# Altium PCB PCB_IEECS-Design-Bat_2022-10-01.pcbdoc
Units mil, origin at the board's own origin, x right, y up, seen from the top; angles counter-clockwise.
Board outline 3665.03 x 2799.77 mil, 2 copper layers (Top Layer, Bottom Layer); 64 components, 39 nets, 166 pads, 43 vias.
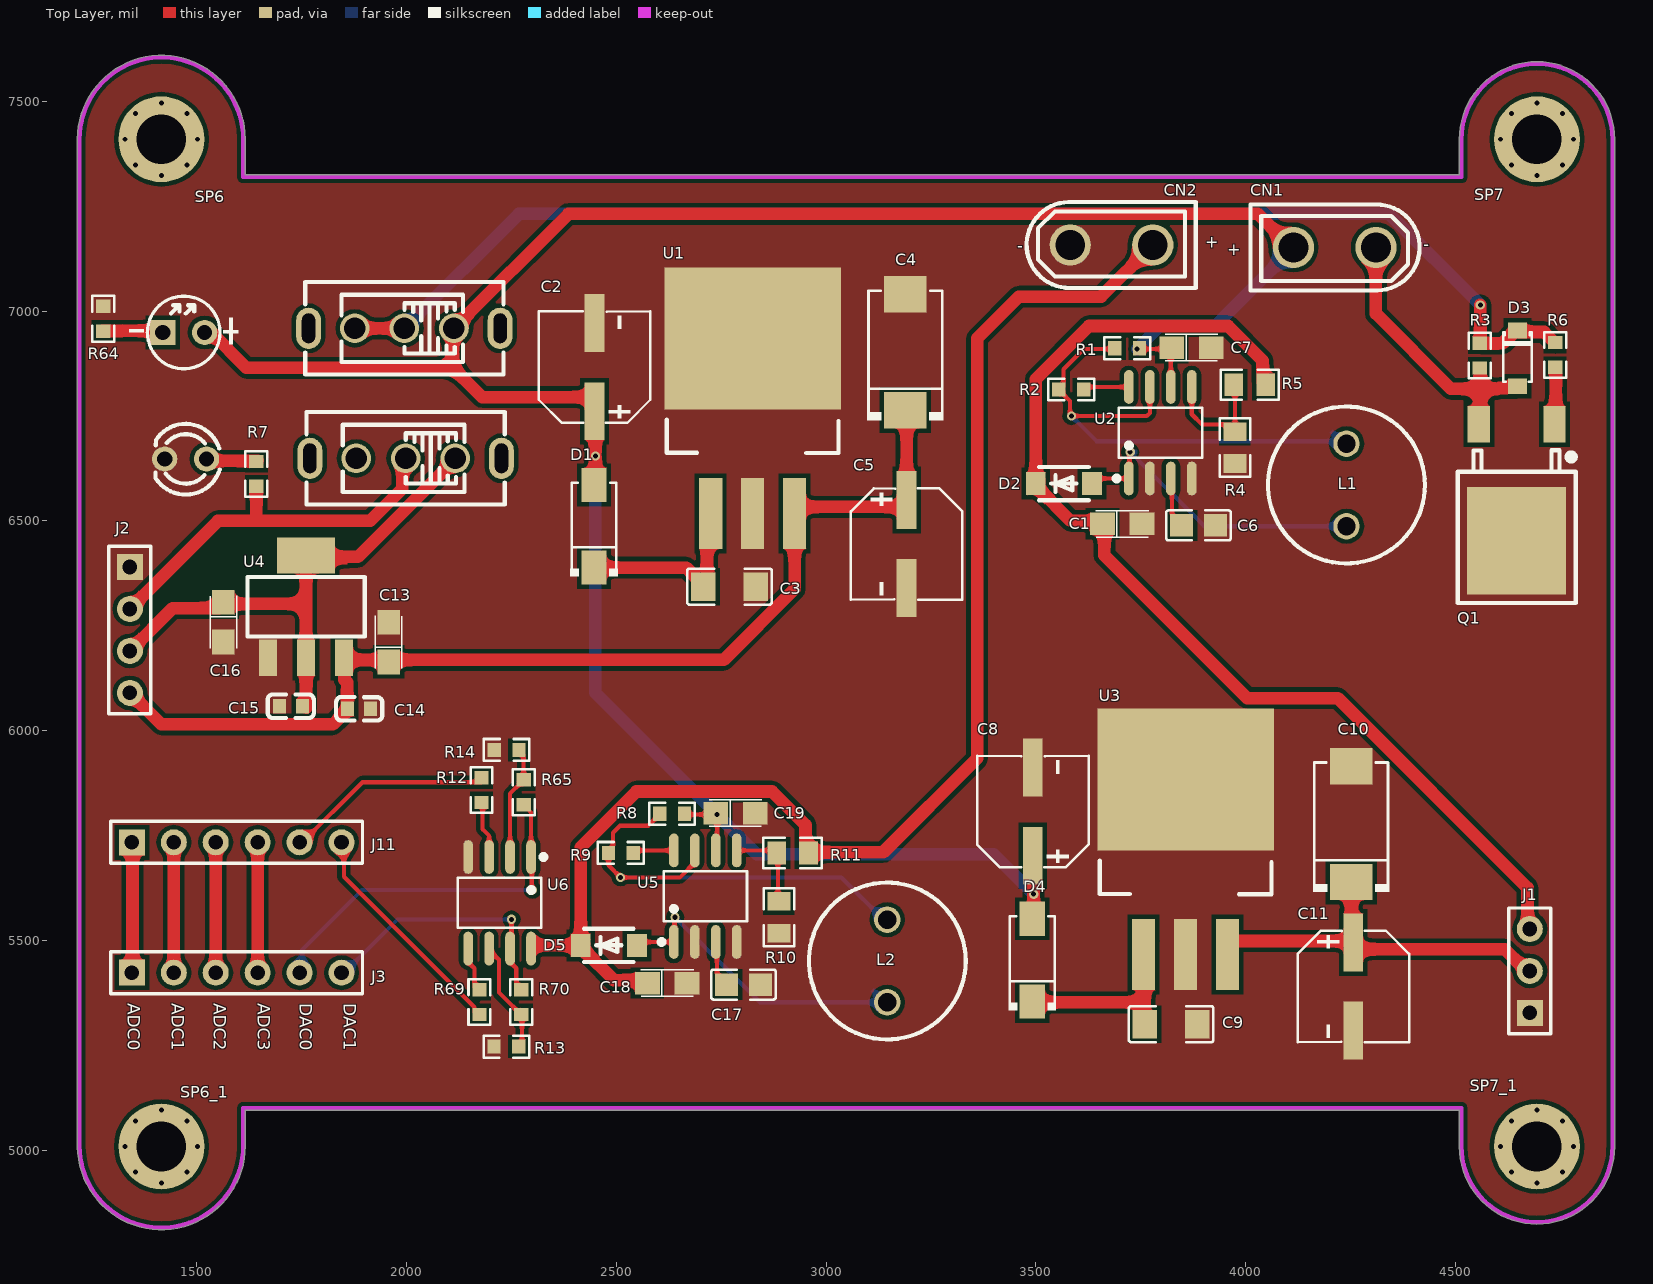
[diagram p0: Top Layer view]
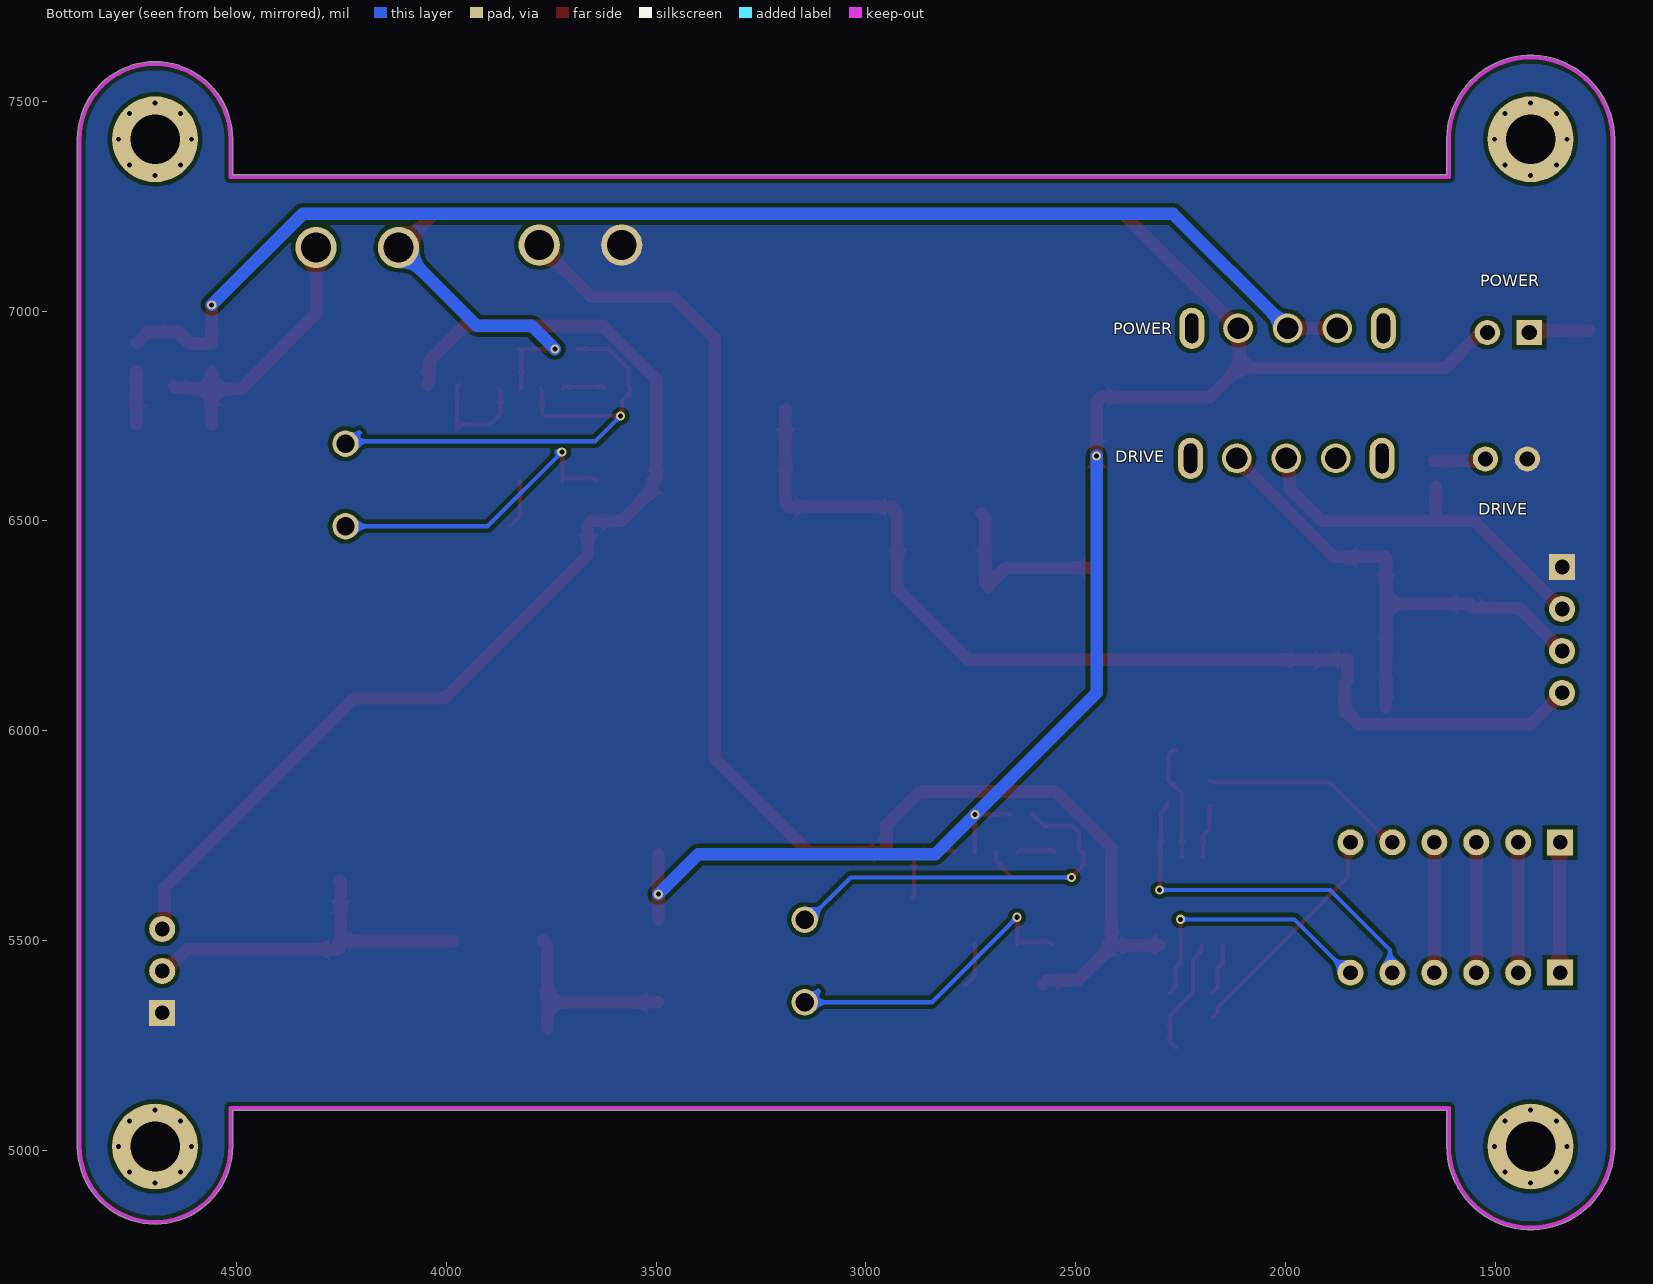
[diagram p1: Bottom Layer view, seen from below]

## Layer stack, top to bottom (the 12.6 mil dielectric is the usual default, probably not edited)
Top Solder: solder mask 0.4, Solder Resist, Dk 3.5
Top Layer: signal copper 1.4
Dielectric1: dielectric 12.6, FR-4, Dk 4.8
Bottom Layer: signal copper 1.4
Bottom Solder: solder mask 0.4, Solder Resist, Dk 3.5

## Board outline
1214.98,5009.8 cw(c1415,5010) 1214.98,5010 cw(c1220,5010) 1214.98,5010.03 1214.98,7410 cw(c1415,7410) 1615.02,7410 1615.02,7325.01 4509.99,7325.01 4509.99,7410 cw(c4695,7410) 4880.01,7410 4880.01,5008.43 cw(c4695,5008.43) 4509.99,5008.43 4509.99,5094.98 1615.02,5094.98 1615.02,5010 cw(c1415,5010) 1214.99,5008.13 cw(c1220,5008.43) 1214.98,5008.43

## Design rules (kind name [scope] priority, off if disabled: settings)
Clearance [All] p1: gap=10 ignorepadtopadclearanceinfootprint=FALSE except(0: Arc-Hole Track-Hole SMDPad-Hole THPad-Hole Via-Hole Fill-Hole Poly-Hole Region-Hole Text-Hole)
Height [All] p1: minheight=-35795.94 maxheight=71537.31 prefheight=71537.31
PolygonConnect [All] p1: connectstyle=Direct reliefconductorwidth=10 reliefentries=4 polygonreliefangle="90 Angle" airgapwidth=10
RoutingVias [All] p1: holewidth=28 width=50 viastyle="Through Hole" minholewidth=28 minwidth=50 maxholewidth=28 maxwidth=50
SolderMaskExpansion [All] p1: expansion=4
Width [All] p1: maxlimit=30 minlimit=10 preferedwidth=10 minimp=50.000000 maximp=50.000000 favimp=50.000000
29 further rules are at their usual default settings.

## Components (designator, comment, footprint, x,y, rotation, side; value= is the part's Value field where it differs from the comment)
C1 "10u" CASE-A-3216 3710,6490 r0 top
C2 "100uF" 110uf 2450,6870 r0 top
C3 "470nF" CAP1206 2770,6350 r0 top
C4 "22uF" CAP-SMD 3190,6895 r0 top
C5 "220uF" 220uf 3185,6440 r0 top
C6 "470pF" CAP0805 3890.55,6490 r0 top
C7 "10u" CASE-A-3216 3875,6910 r0 top
C8 "100uF" 110uf 3495,5809.84 r0 top
C9 "470nF" CAP1206 3823.09,5306.6 r0 top
C10 "22uF" CAP-SMD 4253.37,5770 r0 top
C11 "220uF" 220uf 4250,5385 r0 top
C13 "10u" CASE-A-3216 1960,6215 r90 top
C14 "100nf" CAP0603 1885.43,6055 r180 top
C15 "100nf" CAP0603 1725,6055 r0 top
C16 "10u" CASE-A-3216 1560,6255 r270 top
C17 "470pF" CAP0805 2805.55,5395 r0 top
C18 "10u" CASE-A-3216 2625,5395 r0 top
C19 "10u" CASE-A-3216 2787.76,5800 r0 top
CN1 "XT30UPB-M" XT30 4200,7140 r90 top
CN2 "XT30UPB-M" XT30 3693.27,7170 r270 top
D1 "SS54_C727065" SS54 2450,6485 r270 top
D2 "1N5819HW-7-F" Diode 3575,6595.85 r0 top
D3 "BZT52C16_C216724" BTZ52C16 4650,6886.43 r270 top
D4 "SS54_C727065" SS54 3495,5450.69 r270 top
D5 "1N5819HW-7-F" Diode 2490,5495 r0 top
DRIVE "TJ-L3FYTXHAMCGLFLC0A-A5" LED-LARGE-2 1470.35,6645 r0 bottom (schematic designator LED3)
DRIVE "SS-12F44-G5" Switch 2000.35,6645 r0 bottom (schematic designator SW2)
J1 "HDR-M-2.54_1x3" Pin1X3 4680,5425 r0 top
J2 "HDR-M-2.54_1x4" Pin1X4 1335.86,6240.59 r90 top
J3 "HDR-M-2.54_1x6" Pin1x6 1598.45,5415 r0 top
J11 "HDR-M-2.54_1x6" Pin1x6 1598.45,5725.85 r0 top
L1 "470uH" L 4240,6580 r0 top
L2 "470uH" L 3145,5445 r0 top
POWER "TJ-L3FYTGHGMCGLFLC2G-A5" LED-LARGE-1 1475.35,6950 r180 bottom (schematic designator LED1)
POWER "SS-12F44-G5" Switch 1997.23,6955 r0 bottom (schematic designator SW1)
Q1 "IRLR7843TRPBF" IRLR7843 4650,6560.53 r0 top
R1 "0.22R" RES0603 3710,6910 r0 top
R2 "180R" RES0603 3592.64,6815 r180 top
R3 "100k" RES0603 4560,6886.43 r90 top
R4 "2k" RES0805 3975,6680 r270 top
R5 "14k" RES0805 4005,6825 r0 top
R6 "1k" RES0603 4740,6887.92 r90 top
R7 "330" RES0603 1640,6620 r270 top
R8 "0.22R" RES0603 2625,5800 r0 top
R9 "180R" RES0603 2518.51,5710 r180 top
R10 "1.5k" RES0805 2887.76,5560 r270 top
R11 "13k" RES0805 2915,5708.41 r0 top
R12 "10k" RES0603 2180,5850.35 r90 top
R13 "15k" RES0603 2230,5245 r0 top
R14 "15k" RES0603 2230.34,5952.42 r0 top
R64 "510" RES0603 1275,6990 r270 top
R65 "30k" RES0603 2281.05,5845 r90 top
R69 "10k" RES0603 2175,5345 r90 top
R70 "30k" RES0603 2275,5345 r90 top
SP6 "M3铜柱" M3-MountHole-Plated 1415,7410 r0 top (schematic designator SP2)
SP6_1 "M3铜柱" M3-MountHole-Plated 1415,5008.43 r0 top (schematic designator SP2)
SP7 "M3铜柱" M3-MountHole-Plated 4695,7410 r0 top (schematic designator SP2)
SP7_1 "M3铜柱" M3-MountHole-Plated 4695,5008.43 r0 top (schematic designator SP2)
U1 "LM2940S-5.0/NOPB" LM2940S 2782.7,6756.79 r0 top
U2 "MC34063ADR" MC34063 3800,6705 r0 top
U3 "LM2940S-5.0/NOPB" LM2940S 3815,5705 r0 top
U4 "AMS1117-3.3_C347222" AMS1117 1760,6290 r0 top
U5 "MC34063ADR" MC34063 2715,5600 r0 top
U6 "LM358DR2G" LM358 2225,5593.5 r180 top

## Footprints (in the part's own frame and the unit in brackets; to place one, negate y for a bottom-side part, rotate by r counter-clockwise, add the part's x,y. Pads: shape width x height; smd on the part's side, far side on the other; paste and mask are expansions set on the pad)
110uf [mm]
  rect 1.2x3.5 smd: 1(-0.053,-2.75) 2(-0.053,2.59)
  silkscreen extent -3.43,-3.46 3.32,3.3, body extent -3.37,-3.73 3.23,4.07, height 7.75
220uf [mm]
  rect 1.2x3.5 smd: 1(0.178,2.793) 2(0.178,-2.547)
  silkscreen extent -3.2,-3.25 3.55,3.5, body extent -3.1,-3.82 3.5,3.98, height 7.75
AMS1117 [mm]
  rect 1.1x2.2 smd: 1(-2.297,-2.959) 2(0.003,-2.959) 3(2.303,-2.959)
  rect 3.5x2.2 smd: 4(0.003,3.238)
  silkscreen extent -3.55,-1.66 3.55,1.94, body extent -3.22,-3.43 3.28,3.68, height 1.75
BTZ52C16 [mm]
  rect 0.95x1.15 smd: 1(-1.723,-0.043) 2(1.662,-0.043)
  silkscreen extent -1.61,-0.91 1.38,0.82, body extent -1.93,-0.84 1.75,0.76, height 1.22
CAP0603 [mm]
  rect 0.8x0.9 smd: 1(-0.725,0.076) 2(0.675,0.076)
  silkscreen extent -1.43,-0.63 1.36,0.79, body extent -0.93,-0.32 0.67,0.48, height 0.8
CAP0805 [mm]
  rect 1.41x1.35 smd: 1(0.965,-0.015) 2(-1.095,-0.015)
  silkscreen extent -2.03,-0.92 1.9,0.89, body extent -1.14,-0.69 0.86,0.61, height 1.3
CAP1206 [mm]
  rect 1.485x1.728 smd: 1(1.583,-0.168) 2(-1.602,-0.168)
  silkscreen extent -2.57,-1.26 2.55,0.92, body extent -1.68,-0.96 1.52,0.64, height 1.3
CAP-SMD [mil]
  rect 102.05x86.91 smd: 1(-1.2,-130.94) 2(-1.2,145.54)
  silkscreen extent -92,-154 89,154, body extent -86,-140 84,147, height 167
CASE-A-3216 [mil]
  rect 59.05x53.5 smd: 1(-51.07,3.1) 2(43.42,3.1)
  silkscreen extent -67,-28 59,35, body extent -67,-30 59,33, height 67
Diode [mm]
  rect 1.2x1.4 smd: 1(1.499,-0.177) 2(-1.901,-0.177)
  silkscreen extent -1.7,-1.18 1.3,0.82, body extent -1.95,-1.15 1.7,0.65, height 0.81
IRLR7843 [mm]
  rect 1.35x2.2 smd: 1(2.206,4.319) 3(-2.374,4.319)
  rect 6x6.5 smd: 4(-0.084,-2.748)
  silkscreen extent -3.66,-6.51 3.49,2.74, body extent -3.3,-5.41 3.2,4.51
L [mm]
  round 1.6 hole 1.1: 1(0.02,-2.355) 2(0.02,2.645)
  silkscreen extent -4.73,-4.6 4.77,4.89, body extent -4.7,-4.61 4.81,4.89, height 12.5
LED-LARGE-1 [mil]
  rect 60x60 hole 36: 1(56.95,-0.6)
  round 60 hole 36: 2(-43.05,-0.6)
  body extent -55,-79 87,75, height 118
LED-LARGE-2 [mil]
  round 60 hole 36: 1(52.71,-2.7) 2(-47.29,-2.7)
  body extent -77,-81 65,73, height 118
LM358 [mm]
  oval 0.588x2.045 smd: 1(-1.819,-2.671) 2(-0.549,-2.671) 3(0.721,-2.671) 4(1.991,-2.671) 5(1.991,2.874) 6(0.721,2.874) 7(-0.549,2.874) 8(-1.819,2.874)
  silkscreen extent -2.72,-2.82 2.61,1.62, body extent -2.33,-2.9 2.48,3.1, height 1.72
LM2940S [mm]
  rect 1.4x4.3 smd: 1(-1.466,-6.073) 2(1.074,-6.073) 3(3.614,-6.073)
  rect 10.7x8.6 smd: 4(1.074,4.527)
  silkscreen extent -4.13,-2.41 6.27,-0.39, body extent -4.05,-6.57 6.15,7.66, height 4.5
M3-MountHole-Plated [mm]
  round 5.2 hole 3: 1(0,0)
MC34063 [mm]
  oval 0.588x2.045 smd: 1(-1.981,-2.639) 2(-0.711,-2.639) 3(0.559,-2.639) 4(1.829,-2.639) 5(1.829,2.906) 6(0.559,2.906) 7(-0.711,2.906) 8(-1.981,2.906)
  silkscreen extent -2.88,-2.79 2.45,1.66, body extent -2.46,-2.81 2.35,3.19, height 1.72
Pin1X3 [mil]
  rect 62x62 hole 35: 1(-2.14,-98)
  round 62 hole 35: 2(-2.14,2) 3(-2.14,102)
  silkscreen extent -52,-148 48,152, body extent -52,-148 48,152, height 335
Pin1X4 [mil]
  rect 62x62 hole 35: 1(149.41,-4.14)
  round 62 hole 35: 2(49.41,-4.14) 3(-50.59,-4.14) 4(-150.59,-4.14)
  silkscreen extent -201,-54 199,46, body extent -205,-54 195,46, height 335
Pin1x6 [mil]
  rect 62x62 hole 35: 1(-253.74,7.86)
  round 62 hole 35: 2(-153.74,7.86) 3(-53.74,7.86) 4(46.26,7.86) 5(146.26,7.86) 6(246.26,7.86)
  silkscreen extent -304,-42 296,58, body extent -305,-45 295,125, height 335
RES0603 [mil]
  rect 31.75x34.02 smd: 1(-21.8,1.59) 2(37.51,1.59)
  silkscreen extent -47,-24 62,28, body extent -21,-16 42,16, height 31
RES0805 [mil]
  rect 44.59x54.21 smd: 1(43.14,-0.2) 2(-32.94,-0.2)
  silkscreen extent -64,-36 74,36, body extent -37,-25 42,26, height 24
SS54 [mil]
  rect 81.2x60.59 smd: 1(-100.77,-3.33) 2(96.37,-3.33)
  silkscreen extent -106,-60 117,53, body extent -100,-58 104,53, height 83
Switch [mm]
  round 1.8 hole 1.3: 1(2.93,-0.107) 2(-0.07,-0.107) 3(-3.07,-0.107)
  oval 1.5x2.5 hole 0.8 slot 1.8 at 90 deg: 4(-5.87,-0.107) 5(5.73,-0.107)
  body extent -6.12,-3.27 5.98,3.06, height 11.31
XT30 [mm]
  round 2.5 hole 1.8: 1(0.305,-2.822) 2(0.305,2.178)
  silkscreen extent -2.3,-5.46 2.91,4.78, body extent -2.3,-5.35 5.84,4.85, height 10.7

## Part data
SP6 SP6_1 SP7 SP7_1: library part 铜柱小焊盘, "铜柱"

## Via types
v1: diameter 23.62, hole 11.81, Top Layer to Bottom Layer, 32 vias
v2: diameter 22, hole 12, Top Layer to Bottom Layer, tented both sides, 11 vias

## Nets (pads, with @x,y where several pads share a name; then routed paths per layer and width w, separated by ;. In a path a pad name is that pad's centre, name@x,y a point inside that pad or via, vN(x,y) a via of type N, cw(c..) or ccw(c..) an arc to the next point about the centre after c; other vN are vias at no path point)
ADC-0: J3.1 J11.1 | length 312.6
  Top Layer w30: J3.1@1348.45,5415 1346.3,5417.15 1346.3,5723.7 J11.1@1348.45,5725.85
ADC-1: J3.2 J11.2 | length 313.9
  Top Layer w30: J3.2@1448.45,5415 1444.71,5418.74 1444.71,5722.1 J11.2@1448.45,5725.85
ADC-2: J3.3 J11.3 | length 313.9
  Top Layer w30: J3.3@1548.45,5415 1544.71,5418.74 1544.71,5722.1 J11.3@1548.45,5725.85
ADC-3: J3.4 J11.4 | length 313.9
  Top Layer w30: J3.4@1648.45,5415 1644.71,5418.74 1644.71,5722.1 J11.4@1648.45,5725.85
C6_2: C6.2 U2.3 | length 119.1
  Top Layer w10: U2.3@3825,6595.85 3824.51,6595.36 3824.51,6566.36 3824.7,6566.18 3824.7,6510.98 3845.67,6490 C6.2@3850,6490
D4_2: C9.2 D4.2 U3.1 | length 476.5
  Top Layer w30: D4.2@3495,5352.12 3759.61,5352.12 ; C9.2@3759.61,5290.69 3759.61,5352.12 ; U3.1@3769.86,5498.37 3759.61,5488.12 3759.61,5352.12
DAC-0-O: J11.5 R12.2 | length 498.3
  Top Layer w10: J11.5@1748.45,5725.85 1748.45,5730.83 1894.6,5876.98 2176.98,5876.98 R12.2@2180,5880
DAC-0-OUT: J3.5 R65.1 U6.1 | length 928
  Top Layer w10: R65.1@2278.41,5828.2 2284.1,5822.51 R65.1@2284.1,5817.33 ; R65.1@2280,5820.35 2281.08,5820.35 R65.1@2284.1,5817.33 ; U6.1 U6.1@2296.6,5730.89 ; v2(2300,5620) 2298.3,5621.7 2298.3,5698.3 2300,5700 2300,5727.49 U6.1@2296.6,5730.89 ; R65.1@2284.1,5817.33 2296.6,5804.83 U6.1@2296.6,5730.89
  Bottom Layer w10: J3.5@1748.45,5415 1750.27,5416.82 1750.27,5477.18 1893.09,5620 v2(2300,5620)
DAC-1-O: J11.6 R69.1 | length 545.8
  Top Layer w10: J11.6@1848.45,5725.85 1850.27,5724.03 1850.27,5651.56 2161.4,5340.42 2161.4,5328.95 R69.1@2175,5315.35
DAC-1-OUT: J3.6 R70.2 U6.7 | length 646.9
  Top Layer w10: v2(2250,5550) 2249.86,5549.86 2249.86,5487.14 2250,5487 2249.12,5486.12 2249.12,5445.59 2261.4,5433.31 2261.4,5388.26 R70.2@2275,5374.66
  Bottom Layer w10: J3.6@1848.45,5415 1848.45,5419.99 1978.46,5550 v2(2250,5550)
GND: C1.2 C2.2 C3.1 C4.2 C5.2 C6.1 C7.2 C8.2 C9.1 C10.2 C11.2 C13.2 C14.1 C15.1 C16.2 C17.1 C18.2 C19.2 CN2.1 DRIVE.2@1423.05,6647.7 J1.1 J2.1 Q1.4 R4.1 R10.1 R13.1 R14.1 R64.1 U1.2 U1.4 U2.2 U2.4 U3.2 U3.4 U4.1 U5.2 U5.4 U6.4
GNDIN: CN1.1 D3.2 Q1.3 R3.1 | length 696.8
  Top Layer w30: CN1.1@4308.43,7150 4310.88,7147.55 4310.88,6994.12 4490,6815 4560,6815 ; Q1.3@4559.84,6730.4 4560,6730.56 4560,6815 ; R3.1@4560,6854.93 4560,6815 ; D3.2@4650,6819.79 4647.49,6817.28 4604.71,6817.28 4602.43,6815 4560,6815
L1_1: D2.1 L1.1 U2.1 | length 747.6
  Top Layer w10: D2.1@3641.93,6595.85 3647.2,6601.12 3719.73,6601.12 3725,6595.85 3723.5,6597.35 3723.5,6662.65 v2(3725,6664.15)
  Bottom Layer w10: v2(3725,6664.15) 3901.88,6487.27 4234.3,6487.27 L1.1@4240,6481.57
L1_2: L1.2 R1.1 R2.2 U2.7 | length 1199.1
  Top Layer w10: R1.1 3686.61,6910 3614.47,6910 3566,6861.53 3566,6819.86 3561.14,6815 3561.14,6806.26 3581.31,6786.09 3581.31,6753.69 v2(3585,6750) 3764.59,6750 3772,6757.41 3772,6811.15 U2.7@3775,6814.15
  Bottom Layer w10: v2(3585,6750) 3644.85,6690.15 4228.27,6690.15 L1.2@4240,6678.42
LED1_2: POWER.1@1418.39,6949.4 R64.2 | length 151.5
  Top Layer w30: R64.2@1275.35,6953.51 1421.84,6953.51 POWER.1@1425.35,6950
NSLEEP: DRIVE.2@1997.57,6649.2 J2.2 R7.2 | length 926.4
  Top Layer w30: J2.2 1550,6500 1648.45,6500 ; R7.2 1641.59,6506.86 1648.45,6500 ; DRIVE.2@2000.35,6645 1989.75,6634.41 1989.75,6576.91 1912.84,6500 1648.45,6500
Q1_1: Q1.1 R6.1 | length 126.1
  Top Layer w30: R6.1@4740,6856.43 4740,6730.56 Q1.1@4740.16,6730.39
R2_1: R2.1 U2.8 | length 105.6
  Top Layer w10: R2.1@3624.13,6815 3624.13,6818.25 3625.31,6819.43 3719.73,6819.43 U2.8@3724.15,6815
R5_2: R4.2 R5.2 U2.5 | length 288.2
  Top Layer w10: U2.5@3875,6814.15 3872,6811.15 3872,6754.25 3896.01,6730.24 3962.81,6730.24 3975,6718.04 3975,6820 R5.2@3970,6825
R7_1: DRIVE.1@1523.05,6647.7 R7.1 | length 125.8
  Top Layer w30: DRIVE.1@1520.35,6645 1522.36,6642.99 R7.1@1645.35,6642.99
R12_1: R12.1 U6.3 | length 134.4
  Top Layer w10: R12.1@2180,5820.69 2181.09,5820.69 2181.09,5765 2196.6,5749.49 U6.3@2196.6,5703.4 ; U6.3 U6.3@2196.6,5703.4 ; U6.3@2200,5700 U6.3@2196.6,5703.4
R65_2: R14.2 R65.2 U6.2 | length 282.7
  Top Layer w10: U6.2 U6.2@2246.6,5703.4 ; U6.2@2247.99,5702.01 U6.2@2246.6,5703.4 ; R14.2@2260,5952.42 2268.32,5952.42 2278.73,5942 R65.2@2278.73,5881.79 ; R65.2 R65.2@2278.73,5881.79 ; U6.2@2246.6,5703.4 2246.6,5849.66 R65.2@2278.73,5881.79
R69_2: R69.2 U6.5 | length 123.4
  Top Layer w10: U6.5@2150,5487 2149.12,5486.12 2149.12,5445.59 2161.4,5433.31 2161.4,5388.26 R69.2@2175,5374.66
R70_1: R13.2 R70.1 U6.6 | length 280.4
  Top Layer w10: U6.6@2200,5487 2200,5474.58 2220.03,5454.56 2220.03,5375.45 2275,5320.48 2275,5258.6 2261.4,5245 R13.2@2259.66,5245
S$28: 
S$1126: 
SW1_3: D3.1 POWER.2@1994.46,6959.2 POWER.3 R3.2 R6.2 | length 3189.1
  Top Layer w30: POWER.3@1879.13,6955 1883.33,6959.2 1993.04,6959.2 POWER.2@1997.24,6955 ; v2(4560,7015) 4560,6923.56 4560.42,6923.14 4613.25,6923.14 4643.17,6953.06 4648.3,6953.06 4650.81,6950.55 4712.16,6950.55 4738.15,6924.56 R6.2@4740,6924.56
  Bottom Layer w30: POWER.2@1997.24,6955 1997.24,6961.97 2267.48,7232.21 4342.79,7232.21 v2(4560,7015)
U1_1: C3.2 D1.2 U1.1 | length 458.9
  Top Layer w30: D1.2@2450,6386.43 2452.2,6388.63 2666.47,6388.63 2706.91,6348.18 C3.2 ; C3.2@2708.51,6345 2715.96,6352.45 2715.96,6508.64 U1.1
U5_1: D5.1 L2.1 U5.1 | length 744.5
  Top Layer w10: D5.1@2556.93,5490 2563.05,5496.12 2633.04,5496.12 2639.15,5490 2638.5,5490.66 2638.5,5553.5 v2(2640,5555)
  Bottom Layer w10: v2(2640,5555) 2842.73,5352.27 3139.3,5352.27 L2.1@3145,5346.57
U5_3: C17.2 U5.3 | length 109.1
  Top Layer w10: U5.3@2740,5490.85 2739.51,5490.36 2739.51,5461.36 2739.7,5461.18 2739.7,5415.98 2760.67,5395 C17.2@2765,5395
U5_5: R10.2 R11.2 U5.5 | length 211.4
  Top Layer w10: U5.5@2790,5709.15 2790,5711.35 2793.07,5714.43 2878.88,5714.43 2885,5708.31 2885,5605 R10.2@2890,5600
U5_7: L2.2 R8.1 R9.2 U5.7 | length 1145.2
  Top Layer w10: R9.2 2480.99,5679.01 v2(2510,5650) 2651.25,5650 2690,5688.75 U5.7@2690,5709.15 ; R9.2@2487.01,5710 2491.87,5714.86 2491.87,5756.53 2508.4,5773.06 2575.8,5773.06 2603.2,5800.46 R8.1
  Bottom Layer w10: v2(2510,5650) 3036.09,5650 3142.67,5543.42 L2.2@3145,5543.42
U5_8: R9.1 U5.8 | length 94.7
  Top Layer w10: R9.1@2550,5710 2550,5713.25 2551.18,5714.43 2634.73,5714.43 U5.8@2639.15,5710
VCC: C2.1 C7.1 C8.1 C19.1 CN1.2 D1.1 D4.1 POWER.1@2112.57,6959.2 POWER.2@1518.39,6949.4 R1.2 R8.2 U2.6 U5.6 | length 6233.1
  Top Layer w10: R8.2@2656.5,5800 v2(2740,5800) 2740.33,5799.67 2740.33,5709.48 U5.6@2740,5709.15 ; v2(3741.5,6910) 3827.76,6910 3822,6904.24 U2.6 3822,6817.16 U2.6@3825,6814.15
  Top Layer w30: POWER.2@1525.35,6950 1532.9,6950 1617.9,6865 2110,6865 ; D1.1@2450,6583.57 v2(2450,6655) 2450,6784.42 2439.28,6795.14 2179.86,6795.14 2110,6865 ; D4.1@3495,5549.26 v2(3495,5610) C8.1@3495,5704.73 ; CN1.2@4111.58,7150 4029.37,7232.21 2385.59,7232.21 2115.35,6961.97 2115.35,6955 2110,6949.65 2110,6865
  Bottom Layer w30: v2(2450,6655) 2450,6090 v2(2740,5800) 2835,5705 3400,5705 v2(3495,5610) ; v2(3741.5,6910) 3796.5,6965 3927.26,6965 CN1.2
VCC3V3: C15.2 C16.1 DRIVE.1@2115.68,6649.2 J2.3 U4.2 U4.4 | length 1279.4
  Top Layer w30: J2.3 1442.24,6292.24 1551.35,6292.24 1560,6300.89 1560,6302.24 1760,6302.24 ; C15.2@1760.43,6055 1760.43,6167.57 1760,6168 1760,6302.24 ; DRIVE.1@2118.46,6645 2114.63,6645 1883.78,6414.15 1762.15,6414.15 1760,6412 1760,6302.24
VCC5V_BOARD: C4.1 C5.1 C13.1 C14.2 J2.4 U1.3 U4.3 | length 2513.1
  Top Layer w30: J2.4 1415,6015 1823.85,6015 1858.13,6049.28 1858.13,6114.72 1851.78,6121.06 1851.78,6166.77 1850.55,6168 1851.27,6168.72 1959.04,6168.72 1959.76,6168 1960.29,6168.54 2756.04,6168.54 2925,6337.49 U1.3 ; U1.3@2930,6517.68 2930,6525.94 2937.56,6533.5 3183.38,6533.5 3190,6540.12 3190,6550.12 3192,6552.12 3192,6764.76 C4.1@3190,6766.76
VCC5V_OUT: C10.1 C11.1 J1.2 U3.3 | length 863
  Top Layer w30: 3985,5498.37 C11.1@4253.37,5498.37 ; C10.1 4252.17,5499.78 C11.1 ; C11.1@4255,5480.81 4257.15,5478.66 4618.26,5478.66 4671.92,5425 J1.2@4680,5425 ; C10.1@4255,5642.45 C10.1@4255.28,5642.17
VCC10V: C1.1 D2.2 J1.3 R5.1 | length 2657.3
  Top Layer w30: R5.1@4046.08,6825 4040.85,6830.24 4040.85,6882.3 3958.3,6964.85 3626.89,6964.85 3500.14,6838.1 3500.14,6601.44 3505.73,6595.85 3508.07,6595.85 3508.76,6595.15 3508.76,6574.43 3583.2,6500 3652.76,6500 3663.54,6489.22 3663.54,6418.08 4004.11,6077.5 4220.04,6077.5 4672.41,5625.13 4672.41,5532.59 J1.3@4680,5525
VCC12V: C18.1 CN2.2 D5.2 R11.1 U6.8 | length 3258.9
  Top Layer w30: U6.8@2300.03,5487.85 2420.92,5487.85 D5.2@2423.07,5490 ; C18.1@2577.76,5395 2567.76,5405 2494.24,5405 2423.07,5476.16 D5.2@2423.07,5490 ; CN2.2 3656.02,7035 3460,7035 3360,6935 3360,5933.65 3136.35,5710 2961.08,5710 2950.85,5720.24 2950.85,5775.06 2871.06,5854.85 2547.76,5854.85 2415.14,5722.23 2415.14,5497.93 D5.2@2423.07,5490
pads on no net: DRIVE.3 DRIVE.4 DRIVE.5 POWER.4 POWER.5 SP6.1 SP6_1.1 SP7.1 SP7_1.1
copper on no net:
  other v1: 1415,4921.81 4695,4921.81 1353.75,4947.18 1476.25,4947.18 4633.75,4947.18 4756.25,4947.18 1328.39,5008.43 1501.61,5008.43 4608.39,5008.43 4781.61,5008.43 1353.75,5069.67 1476.25,5069.67 4633.75,5069.67 4756.25,5069.67 1415,5095.04 4695,5095.04 1415,7323.39 4695,7323.39 1353.75,7348.75 1476.25,7348.75 4633.75,7348.75 4756.25,7348.75 1328.39,7410 1501.61,7410 4608.39,7410 4781.61,7410 1353.75,7471.25 1476.25,7471.25 4633.75,7471.25 4756.25,7471.25 1415,7496.61 4695,7496.61

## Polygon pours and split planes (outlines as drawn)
GND on Bottom Layer "Bottom Layer-GND" (solid, remove dead copper, pour order 2): 1000,7755 1015,7740 5005,7740 5005,4695 4990,4680 4980,4690 1015,4690
GND on Top Layer "Top Layer-GND" (solid, remove dead copper, pour order 4): 1010,7775 1025,7760 5015,7760 5015,4715 5000,4700 4990,4710 1025,4710

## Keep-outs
Keep-Out Layer:
  lines w10: 1220,5008.43 1220,7410 cw(c1415,7410) 1610,7410 1610,7320 4515,7320 4515,7410 cw(c4695,7410) 4875,7410 4875,5008.43 cw(c4695,5008.43) 4515,5008.43 4515,5098.43 ; 1220,5010 ccw(c1415,5010) 1610,5010 1610,5100 4515,5100

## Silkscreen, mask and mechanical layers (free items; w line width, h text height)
Top Overlay:
  text "ADC0" at 1325,5350 h50 r270
  text "ADC1" at 1430,5350 h50 r270
  text "ADC2" at 1530,5350 h50 r270
  text "ADC3" at 1635,5350 h50 r270
  text "DAC0" at 1735,5350 h50 r270
  text "DAC1" at 1840,5350 h50 r270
